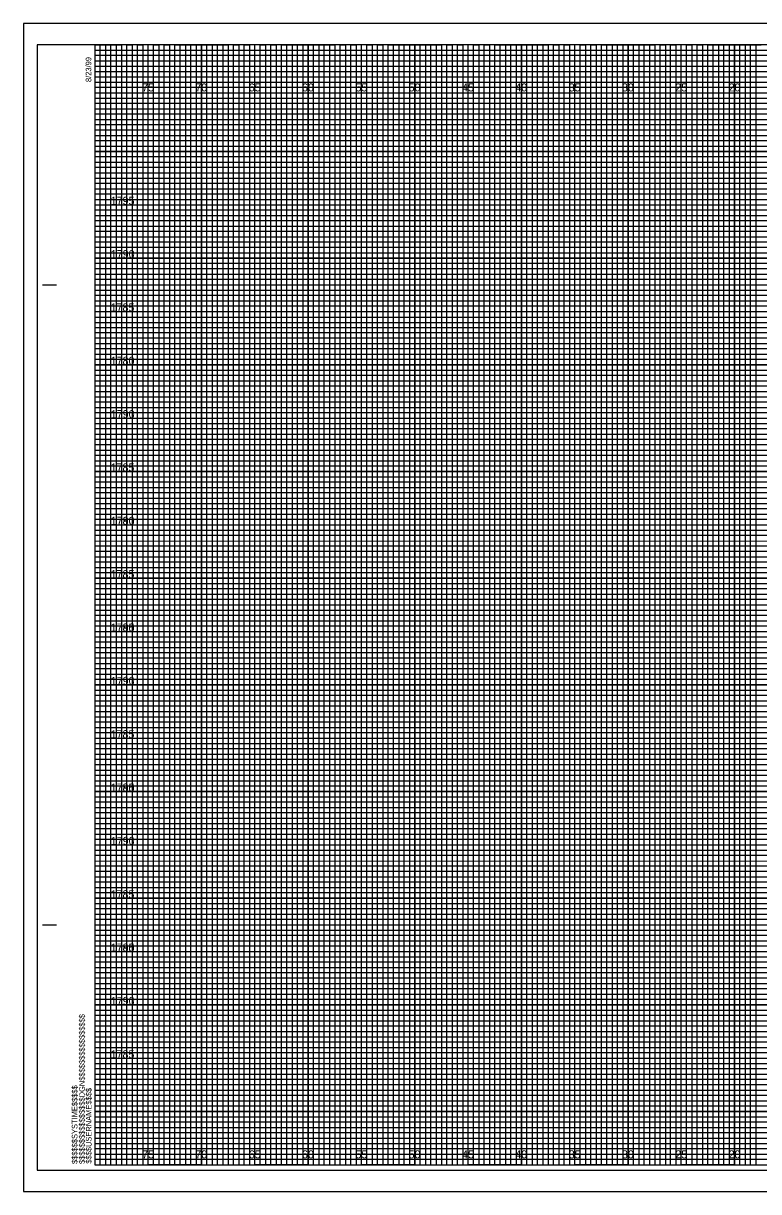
# Model space of a CAD drawing. Extents: x -7 to 205, y -2 to 107.
# Drawn here: x -6.7 to 62.2, y -2.5 to 107 of the extents above; entities that cross this region are included whole.
import ezdxf

# ---------------------------------------------------------------- set-up
doc = ezdxf.new("R2010")
doc.units = 0
for name, color, linetype in [('Prop XS Elevation Labels', 7, 'Continuous'), ('Prop XS Offset Labels', 7, 'Continuous'), ('Sheet Cross Section CELL', 7, 'Continuous'), ('Sheet Cross Section Grid Major CELL', 7, 'Continuous'), ('Sheet Cross Section Grid Middle CELL', 7, 'Continuous'), ('Sheet Cross Section Grid Minor 1 CELL', 7, 'Continuous'), ('Sheet Cross Section Grid Minor 2 CELL', 7, 'Continuous'), ('Sheet Cutting Line CELL', 7, 'Continuous'), ('Sheet DOT Grid CELL', 7, 'Continuous'), ('Sheet Plot Border Inside CELL', 7, 'Continuous'), ('Sheet Plot Border Outside CELL', 7, 'Continuous')]:
    doc.layers.add(name, color=color, linetype=linetype)

msp = doc.modelspace()

# ---------------------------------------------------------------- linework, layer by layer
at = {"layer": 'Sheet Cross Section CELL'}
for p, q in [((-4.9, 82.5), (-3.65, 82.5)), ((-4.85, 82.5), (-3.6, 82.5)), ((-4.9, 22.5), (-3.65, 22.5)), ((-4.85, 22.5), (-3.6, 22.5)), ((0, 0), (0, 0)), ((0, 0), (0, 0)), ((0, 0), (0, 0)), ((0, 0), (0, 0)), ((0, 0), (0, 0)), ((0, 0), (0, 0)), ((0, 0), (0, 0))]:
    msp.add_line(p, q, dxfattribs=at)
msp.add_lwpolyline([(160, 105), (0, 105), (0, 0), (160, 0)], close=True, dxfattribs=at)
at = {"layer": 'Sheet Cross Section Grid Major CELL'}
for p, q in [((5, 105), (0, 105)), ((5, 0), (5, 105)), ((15, 105), (10, 105)), ((10, 105), (10, 0)), ((15, 0), (15, 105)), ((25, 105), (20, 105)), ((20, 105), (20, 0)), ((25, 0), (25, 105)), ((35, 105), (30, 105)), ((30, 105), (30, 0)), ((35, 0), (35, 105)), ((45, 105), (40, 105)), ((40, 105), (40, 0)), ((45, 0), (45, 105)), ((55, 105), (50, 105)), ((50, 105), (50, 0)), ((55, 0), (55, 105)), ((65, 105), (60, 105)), ((60, 105), (60, 0)), ((10, 0), (5, 0)), ((20, 0), (15, 0)), ((30, 0), (25, 0)), ((40, 0), (35, 0)), ((50, 0), (45, 0)), ((60, 0), (55, 0))]:
    msp.add_line(p, q, dxfattribs=at)
for points in [[(0, 100), (160, 100), (160, 95), (0, 95)], [(0, 90), (160, 90), (160, 85), (0, 85)], [(0, 80), (160, 80), (160, 75), (0, 75)], [(0, 70), (160, 70), (160, 65), (0, 65)], [(0, 60), (160, 60), (160, 55), (0, 55)], [(0, 50), (160, 50), (160, 45), (0, 45)], [(0, 40), (160, 40), (160, 35), (0, 35)], [(0, 30), (160, 30), (160, 25), (0, 25)], [(0, 20), (160, 20), (160, 15), (0, 15)], [(0, 10), (160, 10), (160, 5), (0, 5)]]:
    msp.add_lwpolyline(points, dxfattribs=at)
at = {"layer": 'Sheet Cross Section Grid Middle CELL'}
for points in [[(0, 105), (2.5, 105), (2.5, 0), (7.5, 0), (7.5, 105), (12.5, 105), (12.5, 0), (17.5, 0), (17.5, 105), (22.5, 105), (22.5, 0), (27.5, 0), (27.5, 105), (32.5, 105), (32.5, 0), (37.5, 0), (37.5, 105), (42.5, 105), (42.5, 0), (47.5, 0), (47.5, 105), (52.5, 105), (52.5, 0), (57.5, 0), (57.5, 105), (62.5, 105)], [(0, 102.5), (137.5, 102.5)], [(0, 92.5), (160, 92.5), (160, 97.5), (0, 97.5)], [(0, 82.5), (160, 82.5), (160, 87.5), (0, 87.5)], [(0, 72.5), (160, 72.5), (160, 77.5), (0, 77.5)], [(0, 62.5), (160, 62.5), (160, 67.5), (0, 67.5)], [(0, 52.5), (160, 52.5), (160, 57.5), (0, 57.5)], [(0, 42.5), (160, 42.5), (160, 47.5), (0, 47.5)], [(0, 32.5), (160, 32.5), (160, 37.5), (0, 37.5)], [(0, 22.5), (160, 22.5), (160, 27.5), (0, 27.5)], [(0, 12.5), (160, 12.5), (160, 17.5), (0, 17.5)], [(0, 2.5), (160, 2.5), (160, 7.5), (0, 7.5)]]:
    msp.add_lwpolyline(points, dxfattribs=at)
at = {"layer": 'Sheet Cross Section Grid Minor 1 CELL'}
for p, q in [((0, 104.5), (130, 104.5)), ((130, 103.99), (0, 103.99)), ((0, 103.99), (0, 103.5)), ((0, 103.5), (130, 103.5)), ((130, 102.95), (0, 102.95)), ((0, 102.95), (0, 102)), ((0, 102), (160, 102))]:
    msp.add_line(p, q, dxfattribs=at)
for points in [[(0, 101.5), (135, 101.5), (160, 101.5), (160, 101), (0, 101)], [(0, 100.5), (160, 100.5), (160, 99.5), (0, 99.5)], [(0, 99), (160, 99), (160, 98.5), (0, 98.49)], [(0, 98), (160, 98), (160, 97), (0, 97)], [(0, 96.5), (160, 96.5), (160, 96), (0, 96)], [(0, 95.5), (160, 95.5), (160, 94.5), (0, 94.5)], [(0, 94), (160, 94), (160, 93.5), (0, 93.5)], [(0, 93), (160, 93), (160, 92), (0, 92)], [(0, 91.5), (160, 91.5), (160, 91), (0, 91)], [(0, 90.5), (160, 90.5), (160, 89.5), (0, 89.5)], [(0, 89), (160, 89), (160, 88.5), (0, 88.5)], [(0, 88), (160, 88), (160, 86.98), (160, 86.5), (160, 86), (0, 86)], [(0, 87), (160, 87), (160, 86.5), (0, 86.5)], [(0, 85.5), (160, 85.5), (160, 84.5), (0, 84.52)], [(0, 84.52), (160, 84.5), (160, 84), (0, 84)], [(0, 83.5), (160, 83.5), (160, 83), (0, 83)], [(0, 82), (160, 82), (160, 81.5), (0, 81.5)], [(0, 81), (160, 81), (160, 80.5), (0, 80.5)], [(-0.04, 79.45), (160, 79.45), (160, 78.94), (-0.04, 78.94)], [(0, 78.5), (160, 78.5), (160, 78), (0, 78)], [(0, 77), (160, 77), (160, 76.5), (0, 76.5)], [(0, 76), (160, 76), (160, 75.5), (0, 75.5)], [(0, 74.5), (160, 74.5), (160, 74), (0, 74)], [(0, 73.5), (160, 73.5), (160, 73), (0, 73)], [(0, 72), (160, 72), (160, 71.5), (0, 71.5)], [(0, 71), (160, 71), (160, 70.5), (0, 70.5)], [(0, 69.5), (160, 69.5), (160, 68.99), (0, 69)], [(0, 68.5), (160, 68.5), (160, 68), (0, 68)], [(0, 67), (160, 67), (160, 66.5), (0, 66.5)], [(0, 66), (160, 66), (160, 65.5), (0, 65.5)], [(0, 64.5), (160, 64.5), (160, 64), (0, 64)], [(0, 63.5), (160, 63.5), (160, 63), (0, 63)], [(0, 62), (160, 62), (160, 61.5), (0, 61.5)], [(0, 61), (160, 61), (160, 60.5), (0, 60.5)], [(0, 59.5), (160, 59.5), (160, 59), (0, 59)], [(0, 58.5), (160.03, 58.45), (160, 58), (0, 58)], [(0, 57), (160, 57), (160, 56.5), (0, 56.5)], [(0, 56), (160, 56), (160, 55.5), (0, 55.5)], [(0, 54.5), (160, 54.5), (160, 54), (0, 54)], [(0, 53.5), (160, 53.5), (160, 53), (0, 53)], [(0, 52), (160, 52), (160, 51.5), (0, 51.5)], [(0, 51), (160, 51), (160, 50.5), (0, 50.5)], [(0, 49.5), (160, 49.5), (160, 49), (0, 49)], [(0, 48.5), (160, 48.5), (160, 48), (0, 48)], [(0, 47), (160, 47), (160, 46.5), (0, 46.5)], [(0, 46), (160, 46), (160, 45.5), (0, 45.5)], [(0, 44.5), (160, 44.5), (160, 44), (0, 44)], [(0, 43.5), (160, 43.5), (160, 43), (0, 43)], [(0, 42), (160, 42), (160, 41.5), (0, 41.5)], [(0, 41), (160, 41), (160, 40.5), (0, 40.5)], [(0, 39.5), (160, 39.5), (160, 38.99), (0, 39)], [(0, 38.5), (160, 38.5), (160, 38), (0, 38)], [(0, 37), (160, 37), (160, 36.5), (0, 36.5)], [(0, 36), (160, 36), (160, 35.5), (0, 35.5)], [(0, 34.5), (160, 34.5), (160, 34), (0, 34)], [(0, 33.5), (160, 33.5), (160, 33), (0, 33)], [(0, 32), (160, 32), (160, 31.5), (0, 31.5)], [(0, 31), (160, 31), (160, 30.5), (0, 30.5)], [(0, 29.5), (160, 29.5), (160, 29), (0, 29)], [(0, 28.5), (160.03, 28.46), (160, 28), (0, 28)], [(0, 27), (160, 27), (160, 26.5), (0, 26.5)], [(0, 26), (160, 26), (160, 25.5), (0, 25.5)], [(0, 24.5), (160, 24.5), (160, 24), (0, 24)], [(0, 23.5), (160, 23.5), (160, 23), (0, 23)], [(0, 22), (160, 22), (160, 21.5), (0, 21.5)], [(0, 21), (160, 21), (160, 20.5), (0, 20.5)], [(0, 19.5), (160, 19.5), (160, 19), (0, 19)], [(0, 18.5), (160, 18.5), (160, 18), (0, 18)], [(0, 17), (160, 17), (160, 16.5), (0, 16.5)], [(0, 16), (160, 16), (160, 15.5), (0, 15.5)], [(0, 14.5), (160, 14.5), (160, 14), (0, 14)], [(0, 13.5), (160, 13.5), (160, 13), (0, 13)], [(0, 12), (160, 12), (160, 11.5), (0, 11.5)], [(0, 11), (160, 11), (160, 10.5), (0, 10.5)], [(0, 9.5), (160, 9.5), (160, 9), (0, 9)], [(0, 8.5), (160, 8.5), (160, 8), (0, 8)], [(0, 7), (160, 7), (160, 6.5), (0, 6.5)], [(0, 6), (160, 6), (160, 5.5), (0, 5.5)], [(0, 4.5), (160, 4.5), (160, 4), (0, 4)], [(0, 3.5), (160, 3.5), (160, 3), (0, 3)], [(0, 2), (160, 2), (160, 1.5), (0, 1.5)], [(0, 1), (160, 1), (160, 0.5), (0, 0.5)]]:
    msp.add_lwpolyline(points, dxfattribs=at)
at = {"layer": 'Sheet Cross Section Grid Minor 2 CELL'}
for points in [[(0, 0), (0.5, 0), (0.5, 105), (1, 105), (1, 0)], [(1, 0), (1.5, 0), (1.5, 105), (2, 105), (2, 0)], [(2.5, 0), (3, 0), (3, 105), (3.5, 105), (3.5, 0)], [(3.5, 0), (4, 0), (4, 105), (4.5, 105), (4.5, 0)], [(5, 0), (5.5, 0), (5.5, 105), (6, 105), (6, 0)], [(6, 0), (6.5, 0), (6.5, 105), (7, 105), (7, 0)], [(7.5, 0), (8, 0), (8, 105), (8.5, 105), (8.5, 0)], [(8.5, 0), (9, 0), (9, 105), (9.5, 105), (9.5, 0)], [(10, 0), (10.5, 0), (10.5, 105), (11, 105), (11, 0)], [(11, 0), (11.5, 0), (11.5, 105), (12, 105), (12, 0)], [(12.5, 0), (13, 0), (13, 105), (13.5, 105), (13.5, 0)], [(13.5, 0), (14, 0), (14, 105), (14.5, 105), (14.5, 0)], [(15, 0), (15.5, 0), (15.5, 105), (16, 105), (16, 0)], [(16, 0), (16.5, 0), (16.5, 105), (17, 105), (17, 0)], [(17.5, 0), (18, 0), (18, 105), (18.5, 105), (18.5, 0)], [(18.5, 0), (19, 0), (19, 105), (19.5, 105), (19.5, 0)], [(20, 0), (20.5, 0), (20.5, 105), (21, 105), (21, 0)], [(21, 0), (21.5, 0), (21.5, 105), (22, 105), (22, 0)], [(22.5, 0), (23, 0), (23, 105), (23.5, 105), (23.5, 0)], [(23.5, 0), (24, 0), (24, 105), (24.5, 105), (24.5, 0)], [(25, 0), (25.5, 0), (25.5, 105), (26, 105), (26, 0)], [(26, 0), (26.5, 0), (26.5, 105), (27, 105), (27, 0)], [(27.5, 0), (28, 0), (28, 105), (28.5, 105), (28.5, 0)], [(28.5, 0), (29, 0), (29, 105), (29.5, 105), (29.5, 0)], [(30, 0), (30.5, 0), (30.5, 105), (31, 105), (31, 0)], [(31, 0), (31.5, 0), (31.5, 105), (32, 105), (32, 0)], [(32.5, 0), (33, 0), (33, 105), (33.5, 105), (33.5, 0)], [(33.5, 0), (34, 0), (34, 105), (34.5, 105), (34.5, 0)], [(35, 0), (35.5, 0), (35.5, 105), (36, 105), (36, 0)], [(36, 0), (36.5, 0), (36.5, 105), (37, 105), (37, 0)], [(37.5, 0), (38, 0), (38, 105), (38.5, 105), (38.5, 0)], [(38.5, 0), (39, 0), (39, 105), (39.5, 105), (39.5, 0)], [(40, 0), (40.5, 0), (40.5, 105), (41, 105), (41, 0)], [(41, 0), (41.5, 0), (41.5, 105), (42, 105), (42, 0)], [(42.5, 0), (43, 0), (43, 105), (43.5, 105), (43.5, 0)], [(43.5, 0), (44, 0), (44, 105), (44.5, 105), (44.5, 0)], [(45, 0), (45.5, 0), (45.5, 105), (46, 105), (46, 0)], [(46, 0), (46.5, 0), (46.5, 105), (47, 105), (47, 0)], [(47.5, 0), (48, 0), (48, 105), (48.5, 105), (48.5, 0)], [(48.5, 0), (49, 0), (49, 105), (49.5, 105), (49.5, 0)], [(50, 0), (50.5, 0), (50.5, 105), (51, 105), (51, 0)], [(51, 0), (51.5, 0), (51.5, 105), (52, 105), (52, 0)], [(52.5, 0), (53, 0), (53, 105), (53.5, 105), (53.5, 0)], [(53.5, 0), (54, 0), (54, 105), (54.5, 105), (54.5, 0)], [(55, 0), (55.5, 0), (55.5, 105), (56, 105), (56, 0)], [(56, 0), (56.5, 0), (56.5, 105), (57, 105), (57, 0)], [(57.5, 0), (58, 0), (58, 105), (58.5, 105), (58.5, 0)], [(58.5, 0), (59, 0), (59, 105), (59.5, 105), (59.5, 0)], [(60, 0), (60.5, 0), (60.5, 105), (61, 105), (61, 0)], [(61, 0), (61.5, 0), (61.5, 105), (62, 105), (62, 0)]]:
    msp.add_lwpolyline(points, dxfattribs=at)
at = {"layer": 'Sheet Cutting Line CELL'}
for p, q in [((161.65, 107), (-6.7, 107)), ((-6.7, 107), (-6.7, -2.5)), ((-6.7, -2.5), (161.65, -2.5))]:
    msp.add_line(p, q, dxfattribs=at)
at = {"layer": 'Sheet DOT Grid CELL'}
for p, q in [((5, 0), (5, 105)), ((10, 0), (10, 105)), ((15, 0), (15, 105)), ((20, 0), (20, 105)), ((25, 0), (25, 105)), ((30, 0), (30, 105)), ((35, 0), (35, 105)), ((40, 0), (40, 105)), ((45, 0), (45, 105)), ((50, 0), (50, 105)), ((55, 0), (55, 105)), ((60, 0), (60, 105)), ((0, 100), (160, 100)), ((0, 95), (160, 95)), ((0, 90), (160, 90)), ((0, 85), (160, 85)), ((0, 80), (160, 80)), ((0, 75), (160, 75)), ((0, 70), (160, 70)), ((0, 65), (160, 65)), ((0, 60), (160, 60)), ((0, 55), (160, 55)), ((0, 50), (160, 50)), ((0, 45), (160, 45)), ((0, 40), (160, 40)), ((0, 35), (160, 35)), ((0, 30), (160, 30)), ((0, 25), (160, 25)), ((0, 20), (160, 20)), ((0, 15), (160, 15)), ((0, 10), (160, 10)), ((0, 5), (160, 5))]:
    msp.add_line(p, q, dxfattribs=at)
at = {"layer": 'Sheet Plot Border Inside CELL'}
msp.add_lwpolyline([(-5.4, -0.5), (161.2, -0.5), (161.2, 105), (-5.4, 105)], close=True, dxfattribs=at)
at = {"layer": 'Sheet Plot Border Outside CELL'}
msp.add_lwpolyline([(-6.7, -2.5), (161.65, -2.5), (161.65, 107), (-6.7, 107)], close=True, dxfattribs=at)

# ---------------------------------------------------------------- texts
at = {"layer": 'Prop XS Elevation Labels'}
for s, p in [('1795', (1.49, 90)), ('1790', (1.5, 85)), ('1785', (1.48, 80)), ('1780', (1.49, 75)), ('1790', (1.5, 70)), ('1785', (1.48, 65)), ('1780', (1.49, 60)), ('1790', (1.5, 60)), ('1785', (1.48, 55)), ('1795', (1.49, 50)), ('1780', (1.49, 50)), ('1790', (1.5, 45)), ('1785', (1.48, 40)), ('1795', (1.49, 35)), ('1780', (1.49, 35)), ('1790', (1.5, 30)), ('1785', (1.48, 25)), ('1795', (1.49, 20)), ('1780', (1.49, 20)), ('1790', (1.5, 15)), ('1785', (1.48, 10))]:
    msp.add_text(s, height=0.75, dxfattribs=at).set_placement(p)
at = {"layer": 'Prop XS Offset Labels'}
for s, p in [('75', (4.44, 100.62)), ('70', (9.43, 100.62)), ('65', (14.44, 100.62)), ('60', (19.43, 100.62)), ('55', (24.44, 100.62)), ('50', (29.43, 100.62)), ('45', (34.44, 100.62)), ('40', (39.43, 100.62)), ('35', (44.44, 100.62)), ('30', (49.43, 100.62)), ('25', (54.44, 100.62)), ('20', (59.43, 100.62)), ('75', (4.44, 0.62)), ('70', (9.43, 0.62)), ('65', (14.44, 0.62)), ('60', (19.43, 0.62)), ('55', (24.44, 0.62)), ('50', (29.43, 0.62)), ('45', (34.44, 0.62)), ('40', (39.43, 0.62)), ('35', (44.44, 0.62)), ('30', (49.43, 0.62)), ('25', (54.44, 0.62)), ('20', (59.43, 0.62))]:
    msp.add_text(s, height=0.75, dxfattribs=at).set_placement(p)
at = {"layer": 'Sheet Cross Section CELL'}
for s, p in [('8/23/99', (-0.33, 101.5)), ('$$$$$$$$$$$$$$$$DGN$$$$$$$$$$$$$$$$', (-0.94, 0.09)), ('$$$$$$SYSTIME$$$$$', (-1.63, 0.09)), ('$$$$USERNAME$$$$', (-0.31, 0.12))]:
    msp.add_text(s, height=0.525, rotation=90, dxfattribs=at).set_placement(p)

doc.saveas('drawing.dxf')
